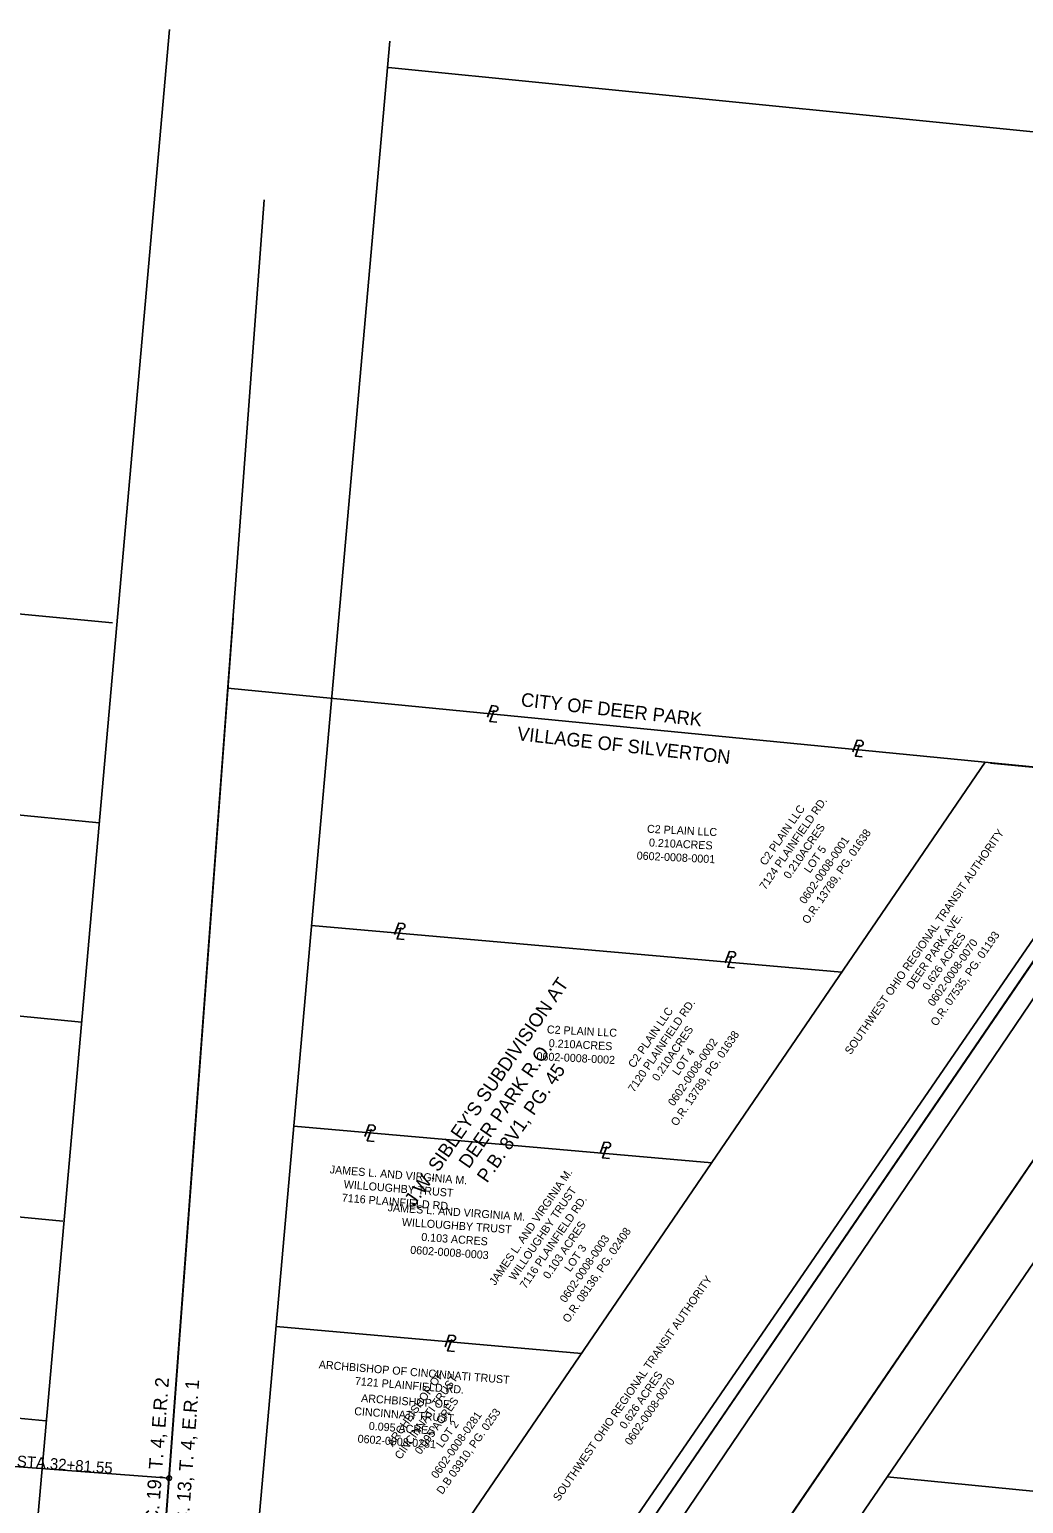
# Model space of a CAD drawing. Extents: x 204354 to 231038, y 361459 to 365260.
# Drawn here: x 220662.5 to 220911.1, y 363831.2 to 364199.5 of the extents above; entities that cross this region are included whole.
import ezdxf

# ---------------------------------------------------------------- set-up
doc = ezdxf.new("R2010")
doc.units = 0
for name, color, linetype in [('CM_Corridor_Point_Control', 7, 'Continuous'), ('CM_Corridor_Range_Conceptual', 7, 'Continuous'), ('DT_P_Contour_Minor', 7, 'Continuous'), ('DT_P_Triangles', 7, 'Continuous'), ('DT_X_Contour_Minor', 7, 'Continuous'), ('MD_P_AGB_B', 7, 'Continuous'), ('MD_P_Intersection_MatchLine', 7, 'Continuous'), ('MD_P_Surface_Asphalt_Concrete_Intermediate_Course', 7, 'Continuous'), ('MD_P_SW_BOT', 7, 'Continuous'), ('MD_P_SW_TOP', 7, 'Continuous'), ('PV_P_Walk', 7, 'Continuous'), ('SC_Shading1', 7, 'Continuous')]:
    doc.layers.add(name, color=color, linetype=linetype)

msp = doc.modelspace()

# ---------------------------------------------------------------- linework, layer by layer
at = {"layer": 'CM_Corridor_Range_Conceptual'}
for p, q in [((221048.44, 364088.77), (220675.48, 363543.03)), ((220572.38, 362161.22), (220713.48, 364052.43)), ((220572.38, 362161.22), (220697.45, 363837.56)), ((220877.01, 363837.92), (221125.78, 363813.14))]:
    msp.add_line(p, q, dxfattribs=at)
at = {"layer": 'DT_P_Triangles'}
msp.add_lwpolyline([(220947.98, 363806.61), (220952.38, 363854.94), (220935.88, 363860.86), (220933.69, 363863.89), (220934.5, 363866.77), (220960.09, 363904.56), (220972.76, 363908.02), (220980.09, 363918.75), (220978.4, 363931.94), (220991.17, 363949.33), (220999.38, 363948.69), (221014.97, 363969.88), (221013.12, 363975.9), (221037.15, 364009.79), (220978.76, 364051.19), (220941.83, 363999.11), (220794.55, 363781.77)], dxfattribs=at)
at = {"layer": 'MD_P_AGB_B'}
msp.add_line((220697.45, 363837.56), (220652.57, 363840.9), dxfattribs=at)
msp.add_circle((220697.45, 363837.56), 0.6, dxfattribs=at)
at = {"layer": 'MD_P_Intersection_MatchLine'}
msp.add_line((220944.67, 364012.24), (220719.24, 363682.39), dxfattribs=at)
at = {"layer": 'MD_P_Surface_Asphalt_Concrete_Intermediate_Course'}
for p, q in [((220652.24, 363231.63), (220712.17, 364034.87)), ((220712.17, 364034.89), (221283.93, 363979.19))]:
    msp.add_line(p, q, dxfattribs=at)
at = {"layer": 'MD_P_SW_BOT'}
for p, q in [((220752.3, 364190.02), (221012.12, 364164.11)), ((220419.9, 363254.43), (221038.63, 364154.27)), ((220683.28, 364051.22), (220445.05, 364074.08)), ((220777.63, 364029.22), (220778.92, 364029.11)), ((220778.38, 364028.53), (220778.38, 364028.53)), ((220868.99, 364020.57), (220870.28, 364020.46)), ((220869.73, 364019.88), (220869.73, 364019.88)), ((220902.84, 364016.19), (220977.85, 364008.97)), ((220679.97, 364001.31), (220569.5, 364011.91)), ((220733.09, 363975.62), (220865.68, 363964.01)), ((220754.39, 363974.89), (220755.68, 363974.78)), ((220755.14, 363974.2), (220755.14, 363974.2)), ((220837.06, 363967.84), (220838.36, 363967.72)), ((220837.81, 363967.15), (220837.81, 363967.15)), ((220675.56, 363951.5), (220564.54, 363962.15)), ((220670.91, 363901.72), (220430.72, 363924.76)), ((220728.65, 363925.51), (220833.15, 363916.36)), ((220746.97, 363924.48), (220748.26, 363924.37)), ((220747.71, 363923.79), (220747.71, 363923.79)), ((220805.78, 363920.19), (220807.07, 363920.08)), ((220806.52, 363919.5), (220806.52, 363919.5)), ((220666.6, 363851.9), (220425.95, 363874.99)), ((220724.21, 363875.4), (220800.56, 363868.72)), ((220767.02, 363871.95), (220768.31, 363871.84)), ((220767.76, 363871.26), (220767.76, 363871.26))]:
    msp.add_line(p, q, dxfattribs=at)
for points in [[(220777.07, 364027.67), (220778.11, 364030.56), (220779.14, 364030.47)], [(220778.73, 364029.46), (220777.68, 364026.59), (220779.42, 364026.43)], [(220868.43, 364019.03), (220869.47, 364021.91), (220870.5, 364021.82)], [(220870.08, 364020.82), (220869.03, 364017.94), (220870.77, 364017.79)], [(220753.83, 363973.35), (220754.87, 363976.23), (220755.9, 363976.14)], [(220755.48, 363975.14), (220754.44, 363972.26), (220756.18, 363972.11)], [(220836.51, 363966.29), (220837.54, 363969.17), (220838.57, 363969.08)], [(220838.16, 363968.08), (220837.11, 363965.2), (220838.85, 363965.05)], [(220746.41, 363922.93), (220747.45, 363925.82), (220748.48, 363925.72)], [(220748.06, 363924.72), (220747.01, 363921.85), (220748.75, 363921.69)], [(220805.22, 363918.64), (220806.26, 363921.53), (220807.28, 363921.44)], [(220806.87, 363920.43), (220805.82, 363917.56), (220807.56, 363917.4)], [(220766.46, 363870.4), (220767.5, 363873.29), (220768.53, 363873.2)], [(220768.11, 363872.19), (220767.06, 363869.32), (220768.8, 363869.16)]]:
    msp.add_lwpolyline(points, dxfattribs=at)
for centre in [(220778.98, 364029.8), (220870.33, 364021.15), (220755.74, 363975.47), (220838.41, 363968.41), (220748.31, 363925.05), (220807.12, 363920.77), (220768.36, 363872.53)]:
    msp.add_arc(centre, 0.69, 265.4688, 76.3259, dxfattribs=at)
at = {"layer": 'MD_P_SW_TOP'}
for q in [(220721.25, 364156.95), (220705.22, 363942.07)]:
    msp.add_line((220580.15, 362265.73), q, dxfattribs=at)
at = {"layer": 'PV_P_Walk'}
for p, q in [((220655.13, 363720.78), (220697.51, 364199.5)), ((220700.81, 363611.12), (220752.66, 364196.62)), ((220742.36, 363666.6), (221067.37, 364142.16)), ((220712.17, 363739.39), (220901.51, 364016.45)), ((220742.36, 363666.6), (220976.44, 364009.11))]:
    msp.add_line(p, q, dxfattribs=at)
at = {"layer": 'SC_Shading1'}
msp.add_lwpolyline([(220700.8, 363611.05), (220705.86, 363668.13), (220715.83, 363682.72), (220719.24, 363682.39), (220944.67, 364012.24), (220976.46, 364009.07), (220742.35, 363666.52), (220738.94, 363666.85), (220700.8, 363611.05)], dxfattribs=at)

# ---------------------------------------------------------------- texts
at = {"layer": 'CM_Corridor_Point_Control'}
for s, p in [('JAMES L. AND VIRGINIA M.', (220737.55, 363913.73)), ('WILLOUGHBY TRUST', (220741.05, 363910.03)), ('7116 PLAINFIELD RD.', (220740.59, 363906.66)), ('ARCHBISHOP OF CINCINNATI TRUST', (220734.81, 363864.99)), ('7121 PLAINFIELD RD.', (220743.85, 363860.84))]:
    msp.add_text(s, height=2, rotation=355.3411, dxfattribs=at).set_placement(p)
at = {"layer": 'DT_P_Contour_Minor'}
for s, height, rotation, p in [('CITY OF DEER PARK', 3.4, 353.5904, (220785.29, 364030.44)), ('VILLAGE OF SILVERTON', 3.4, 353.5904, (220784.34, 364021.94)), ('7124 PLAINFIELD RD.', 2, 55.3581, (220846.53, 363984.38)), ('C2 PLAIN LLC', 2, 55.3581, (220846.57, 363990.43)), ('0.210ACRES', 2, 55.3581, (220852.53, 363987.1)), ('0602-0008-0001', 2, 55.3581, (220856.48, 363980.84)), ('O.R. 13789, PG. 01638', 2, 55.3581, (220857.16, 363975.84)), ('SOUTHWEST OHIO REGIONAL TRANSIT AUTHORITY', 2, 55.3411, (220867.86, 363943.2)), ('LOT 5', 2, 55.3581, (220857.68, 363988.56)), ('DEER PARK AVE.', 2, 55.3411, (220883.28, 363959.53)), ('0.626 ACRES', 2, 55.3411, (220887.26, 363959.31)), ('0602-0008-0070', 2, 55.3411, (220888.58, 363955.25)), ('O.R. 07535, PG. 01193', 2, 55.3411, (220889.3, 363950.31)), ("J.W. SIBLEY'S SUBDIVISION AT", 3.4, 55.2532, (220758.85, 363905.33)), ('7120 PLAINFIELD RD.', 2, 55.7046, (220813.68, 363933.81)), ('C2 PLAIN LLC', 2, 55.7046, (220813.69, 363939.86)), ('0.210ACRES', 2, 55.7046, (220819.67, 363936.56)), ('0602-0008-0002', 2, 55.7046, (220823.65, 363930.34)), ('O.R. 13789, PG. 01638', 2, 55.7046, (220824.36, 363925.34)), ('DEER PARK R.O.', 3.4, 55.2532, (220772.38, 363914.69)), ('LOT 4', 2, 55.7046, (220824.77, 363938.01)), ('P.B. 8V1, PG. 45', 3.4, 55.2532, (220776.94, 363911.12)), ('JAMES L. AND VIRGINIA M.', 2, 55.6707, (220778.96, 363885.55)), ('WILLOUGHBY TRUST', 2, 55.6707, (220783.91, 363886.76)), ('7116 PLAINFIELD RD.', 2, 55.6707, (220786.61, 363884.69)), ('0.103 ACRES', 2, 55.6707, (220792.4, 363887.14)), ('0602-0008-0003', 2, 55.6707, (220796.59, 363881.22)), ('O.R. 08136, PG. 02408', 2, 55.6707, (220797.29, 363876.21)), ('LOT 3', 2, 55.6707, (220797.74, 363888.93)), ('SEC. 19, T. 4, E.R. 2', 3.4, 85.7455, (220694.3, 363820.25)), ('SEC. 13, T. 4, E.R. 1', 3.4, 85.7455, (220701.85, 363819.75)), ('ARCHBISHOP OF ', 2, 54.7031, (220753.38, 363845.25)), ('CINCINNATI TRUST', 2, 54.7031, (220755.3, 363842.07)), ('0.095 ACRES', 2, 54.7031, (220760.32, 363843.29)), ('0602-0008-0281', 2, 54.7031, (220764.4, 363837.28)), ('D.B 03910, PG. 0253', 2, 54.7031, (220765.77, 363833.33)), ('LOT 2', 2, 54.7031, (220765.69, 363844.98))]:
    msp.add_text(s, height=height, rotation=rotation, dxfattribs=at).set_placement(p)
at = {"layer": 'DT_X_Contour_Minor'}
for s, rotation, p in [('C2 PLAIN LLC', 357.2159, (220816.9, 363998.81)), ('0602-0008-0001', 357.2159, (220814.32, 363992.13)), ('0.210ACRES', 357.2159, (220817.39, 363995.39)), ('C2 PLAIN LLC', 357.1071, (220791.86, 363948.69)), ('0.210ACRES', 357.1071, (220792.33, 363945.26)), ('0602-0008-0002', 357.1071, (220789.27, 363942.01)), ('JAMES L. AND VIRGINIA M.', 355.9931, (220752.05, 363904.25)), ('WILLOUGHBY TRUST', 355.9931, (220755.59, 363900.6)), ('0.103 ACRES', 355.9931, (220760.45, 363896.85)), ('0602-0008-0003', 355.9931, (220757.69, 363893.63)), ('SOUTHWEST OHIO REGIONAL TRANSIT AUTHORITY', 55.3411, (220794.9, 363831.63)), ('0.626 ACRES', 55.3411, (220811.5, 363849.66)), ('0602-0008-0070', 55.3411, (220812.83, 363845.6)), ('ARCHBISHOP OF ', 355.7861, (220745.41, 363856.6)), ('CINCINNATI TRUST', 355.7861, (220743.68, 363853.32)), ('0.095 ACRES', 355.7861, (220747.32, 363849.64)), ('0602-0008-0281', 355.7861, (220744.53, 363846.44))]:
    msp.add_text(s, height=2, rotation=rotation, dxfattribs=at).set_placement(p)
at = {"layer": 'MD_P_AGB_B'}
for s, p in [(' STA. ', (220658.27, 363840.52)), ('32+81.55', (220667.56, 363839.82))]:
    msp.add_text(s, height=2.8, rotation=355.7333, dxfattribs=at).set_placement(p)

doc.saveas('drawing.dxf')
